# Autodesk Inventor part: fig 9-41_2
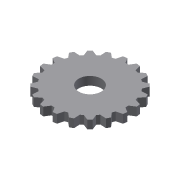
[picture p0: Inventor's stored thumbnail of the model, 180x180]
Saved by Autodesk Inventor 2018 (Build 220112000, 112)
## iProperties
Created: 2013-03
Part Number: fig 9-41_2
Material: Generic
Document SubType Name: Modeling
Designer: CADCIM
Density: 1 g/cm^3
Appearance: Default
Author: CADCIM
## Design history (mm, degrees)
sketch "Sketch1"
  geometry: C1 r 15 at (0, 0); C2 r 4 at (0, 0); 1 further point
  constraints: 2 centre point, 2 coincident
  dimensions: "d0" = 30 diameter of C1; "d2" = 8 diameter of C2
extrude "Extrusion1" new body sketch "Sketch1" distance "d3" = 3; taper "d4" = 0 deg
sketch "Sketch2"
  geometry: L1 (-1.675, 14.906)-(-0.536, 13.106); L2 (-0.536, 13.106)-(0.536, 13.106); L3 (0.536, 13.106)-(1.675, 14.906); L4 (0, 0)-(0, 16.254); C1 r 15 at (0, 0) reference; A1 r 15 centre (0, 0) between (1.675, 14.906) and (-1.675, 14.906); 2 further points
  constraints: 8 end point, 2 point on circle, 2 symmetric about line, 1 centre point, 1 coincident, 1 horizontal, 1 perpendicular
  dimensions: "d5" = 30 diameter of A1
extrude "Extrusion2" cut sketch "Sketch2" distance "d7" = 3; taper "d8" = 0 deg
body "Solid1"
pattern_circular "Circular Pattern1" dims angle "d10" = 360 deg
